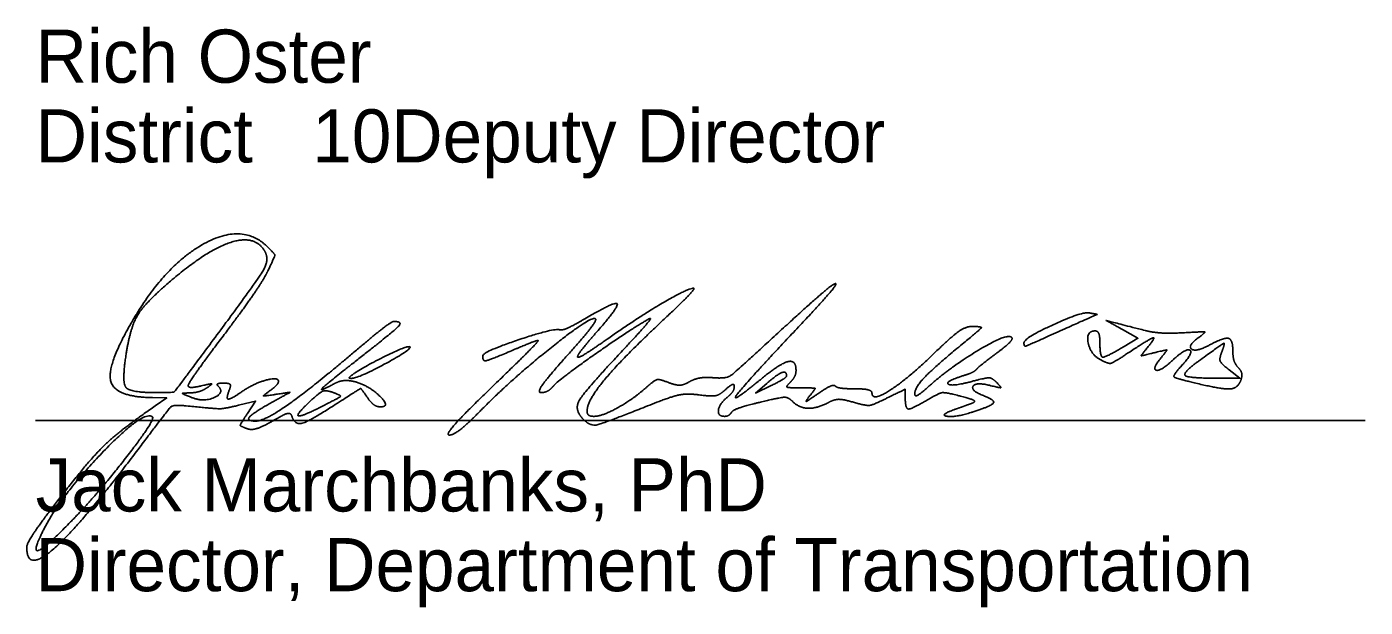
# Model space of a CAD drawing. Extents: x 21.4 to 65.3, y 4 to 26.
# Drawn here: x 45.952 to 49.475, y 11.259 to 12.788 of the extents above; entities that cross this region are included whole.
import ezdxf

# ---------------------------------------------------------------- set-up
doc = ezdxf.new("R2010")
doc.units = 0
doc.layers.add('SH_Data', color=7, linetype='Continuous')
doc.layers.add('SH_Text', color=7, linetype='Continuous')

msp = doc.modelspace()

# ---------------------------------------------------------------- linework, layer by layer
at = {"layer": 'SH_Data'}
msp.add_line((45.9752, 11.751), (49.4752, 11.751), dxfattribs=at)
at = {"layer": 'SH_Text'}
for p, q in [((46.4375, 11.956), (46.4375, 11.956)), ((48.5768, 11.9552), (48.5768, 11.9552)), ((46.8028, 11.8662), (46.8028, 11.8662)), ((47.9518, 11.8682), (47.9518, 11.8682)), ((49.0293, 11.8489), (49.0293, 11.8489)), ((46.758, 11.8245), (46.758, 11.8245)), ((47.1747, 11.8371), (47.1747, 11.8371))]:
    msp.add_line(p, q, dxfattribs=at)
for points in [[(48.8406, 11.9456), (48.877, 11.9671), (48.8363, 11.99)], [(49.0893, 11.8621), (49.1455, 11.8621), (49.1168, 11.8843)], [(47.9001, 11.8485), (47.8705, 11.8229), (47.9112, 11.8425)], [(46.2899, 11.7891), (46.3205, 11.8103), (46.2827, 11.8109)], [(46.5328, 11.7692), (46.554, 11.8016), (46.5123, 11.7915)]]:
    msp.add_lwpolyline(points, dxfattribs=at)
for points in [[(46.2262, 12.0068), (46.3124, 12.1571), (46.5206, 12.2732), (46.5862, 12.2075)], [(46.5773, 12.1983), (46.5513, 12.2403), (46.4252, 12.1992), (46.3299, 12.1176)], [(46.4375, 11.956), (46.5589, 12.1195), (46.5913, 12.1757), (46.5773, 12.1983)], [(46.5862, 12.2075), (46.605, 12.1887), (46.605, 12.1837), (46.5867, 12.1453)], [(46.5867, 12.1453), (46.5758, 12.1223), (46.524, 12.0467), (46.4718, 11.9774)], [(46.3299, 12.1176), (46.2632, 12.0605), (46.2244, 11.9964), (46.2133, 11.9252)], [(47.4799, 11.9652), (47.5605, 12.0219), (47.6918, 12.0991), (47.7075, 12.0991)], [(47.7075, 12.0991), (47.7124, 12.0991), (47.6711, 12.0565), (47.6157, 12.0044)], [(47.9342, 11.9857), (48.0092, 12.0547), (48.0752, 12.1114), (48.081, 12.1114)], [(48.081, 12.1114), (48.0867, 12.1115), (48.0347, 12.0514), (47.9653, 11.9778)], [(47.421, 12.0187), (47.4997, 12.0649), (47.512, 12.0517), (47.4527, 11.9844)], [(47.449, 12.0185), (47.4394, 12.0281), (47.2297, 11.8612), (47.1518, 11.7819)], [(47.5893, 12.0181), (47.5403, 11.9903), (47.3519, 11.858), (47.3387, 11.8421)], [(47.3553, 11.9895), (47.3609, 11.9877), (47.3904, 12.0008), (47.421, 12.0187)], [(47.3712, 11.9181), (47.4175, 11.9699), (47.4525, 12.015), (47.449, 12.0185)], [(47.5241, 11.9391), (47.5703, 11.9884), (47.5996, 12.0239), (47.5893, 12.0181)], [(48.5768, 11.9552), (48.5768, 11.9676), (48.7296, 12.0379), (48.7485, 12.0342)], [(48.7485, 12.0342), (48.7692, 12.0301), (48.77, 12.0306), (48.6483, 11.9759)], [(46.2827, 11.8109), (46.1848, 11.8126), (46.1614, 11.8938), (46.2262, 12.0068)], [(46.8163, 11.9333), (46.8668, 11.9761), (46.9123, 12.0113), (46.9174, 12.0114)], [(46.9174, 12.0114), (46.9423, 12.0119), (46.9189, 11.9863), (46.833, 11.9191)], [(47.152, 11.921), (47.1522, 11.9315), (47.3396, 11.9947), (47.3553, 11.9895)], [(47.4527, 11.9844), (47.4247, 11.9525), (47.4018, 11.9229), (47.4018, 11.9184)], [(47.6157, 12.0044), (47.5161, 11.9107), (47.4268, 11.8025), (47.4268, 11.7755)], [(47.7592, 11.8633), (47.7927, 11.8605), (47.8162, 11.8769), (47.9342, 11.9857)], [(48.3424, 11.9294), (48.3876, 11.9732), (48.4248, 11.9989), (48.4424, 11.9985)], [(48.4424, 11.9985), (48.4667, 11.998), (48.4629, 11.9917), (48.4143, 11.9517)], [(48.7778, 11.911), (48.7513, 11.9252), (48.7403, 11.9866), (48.7643, 11.9866)], [(48.7643, 11.9866), (48.7712, 11.9866), (48.7768, 11.9725), (48.7768, 11.9553)], [(48.8363, 11.99), (48.7934, 12.0142), (48.7925, 12.0142), (48.8955, 11.9878)], [(48.8955, 11.9878), (48.9162, 11.9825), (48.9612, 11.9798), (48.9955, 11.9817)], [(48.9955, 11.9817), (49.0504, 11.9848), (49.0553, 11.9831), (49.0354, 11.9683)], [(46.2914, 11.8241), (46.3381, 11.8241), (46.3426, 11.8282), (46.4375, 11.956)], [(46.4718, 11.9774), (46.4195, 11.908), (46.3768, 11.8473), (46.3768, 11.8426)], [(46.8028, 11.8662), (46.8232, 11.884), (46.9553, 11.9498), (46.9604, 11.9446)], [(46.9604, 11.9446), (46.9666, 11.9385), (46.824, 11.8616), (46.8063, 11.8616)], [(47.1747, 11.8371), (47.2457, 11.9056), (47.301, 11.9616), (47.2976, 11.9616)], [(47.2976, 11.9616), (47.2942, 11.9616), (47.2651, 11.9503), (47.233, 11.9366)], [(47.4018, 11.9184), (47.4018, 11.914), (47.437, 11.935), (47.4799, 11.9652)], [(47.9653, 11.9778), (47.8358, 11.8402), (47.8037, 11.7929), (47.8859, 11.8607)], [(48.4143, 11.9517), (48.3403, 11.8907), (48.2893, 11.8372), (48.2893, 11.8204)], [(48.3237, 11.8382), (48.3773, 11.887), (48.5242, 11.977), (48.5411, 11.9714)], [(48.5411, 11.9714), (48.5495, 11.9686), (48.5343, 11.9499), (48.5072, 11.9297)], [(48.6483, 11.9759), (48.5858, 11.9478), (48.5768, 11.9452), (48.5768, 11.9552)], [(48.7768, 11.9553), (48.7768, 11.9185), (48.7911, 11.9163), (48.8406, 11.9456)], [(48.9002, 11.9408), (48.9246, 11.9704), (48.9088, 11.9666), (48.8525, 11.9294)], [(49.0354, 11.9683), (49.0066, 11.9469), (49.0295, 11.9305), (49.0632, 11.9485)], [(49.0971, 11.9298), (49.107, 11.9556), (49.0987, 11.9525), (49.0361, 11.9069)], [(49.0632, 11.9485), (49.1034, 11.97), (49.1268, 11.9643), (49.1268, 11.9328)], [(46.2133, 11.9252), (46.2019, 11.8518), (46.2233, 11.8241), (46.2914, 11.8241)], [(46.555, 11.7491), (46.578, 11.7491), (46.7041, 11.8379), (46.8163, 11.9333)], [(46.833, 11.9191), (46.7398, 11.8461), (46.7184, 11.8245), (46.7623, 11.848)], [(47.233, 11.9366), (47.1704, 11.9098), (47.1517, 11.9061), (47.152, 11.921)], [(47.3054, 11.8241), (47.2951, 11.8241), (47.324, 11.8654), (47.3712, 11.9181)], [(47.417, 11.7535), (47.3918, 11.7787), (47.4207, 11.8288), (47.5241, 11.9391)], [(48.1768, 11.8226), (48.1768, 11.7998), (48.2721, 11.8612), (48.3424, 11.9294)], [(48.5072, 11.9297), (48.4802, 11.9095), (48.4552, 11.8895), (48.4518, 11.8852)], [(48.8525, 11.9294), (48.8125, 11.9028), (48.7992, 11.8996), (48.7778, 11.911)], [(48.9196, 11.9291), (48.8865, 11.9208), (48.8847, 11.9219), (48.9002, 11.9408)], [(48.9397, 11.9183), (48.9543, 11.9359), (48.952, 11.9371), (48.9196, 11.9291)], [(48.9684, 11.9096), (48.9365, 11.8796), (48.9134, 11.8866), (48.9397, 11.9183)], [(48.9936, 11.8969), (49.0241, 11.9306), (49.0024, 11.9415), (48.9684, 11.9096)], [(49.1168, 11.8843), (49.0964, 11.8999), (49.0907, 11.9132), (49.0971, 11.9298)], [(49.1268, 11.9328), (49.1268, 11.917), (49.1332, 11.8977), (49.141, 11.8899)], [(47.8859, 11.8607), (47.9343, 11.9006), (47.9768, 11.9109), (47.9768, 11.8828)], [(47.9518, 11.8682), (47.9518, 11.8816), (47.9277, 11.8725), (47.9001, 11.8485)], [(47.9768, 11.8828), (47.9768, 11.8739), (47.97, 11.8598), (47.9618, 11.8516)], [(48.4518, 11.8852), (48.4484, 11.881), (48.4329, 11.8735), (48.4174, 11.8687)], [(49.0293, 11.8489), (48.9746, 11.8619), (48.9688, 11.8696), (48.9936, 11.8969)], [(49.0361, 11.9069), (48.9934, 11.8758), (49.0099, 11.8619), (49.0893, 11.8621)], [(49.141, 11.8899), (49.1487, 11.8821), (49.1517, 11.867), (49.1476, 11.8562)], [(46.3768, 11.8426), (46.3768, 11.8378), (46.3923, 11.8375), (46.4112, 11.8419)], [(46.3872, 11.8108), (46.4171, 11.7988), (46.4733, 11.8234), (46.4559, 11.8408)], [(46.4112, 11.8419), (46.4367, 11.8478), (46.4407, 11.8466), (46.4268, 11.8372)], [(46.4559, 11.8408), (46.4513, 11.8454), (46.4576, 11.8491), (46.4698, 11.8491)], [(46.4698, 11.8491), (46.4844, 11.8491), (46.4895, 11.8427), (46.4848, 11.8303)], [(46.5209, 11.8285), (46.5498, 11.8483), (46.6143, 11.8658), (46.6143, 11.8538)], [(46.6143, 11.8538), (46.6143, 11.8493), (46.6046, 11.8385), (46.5927, 11.8298)], [(46.7623, 11.848), (46.7749, 11.8548), (46.7988, 11.8569), (46.8154, 11.8527)], [(46.8063, 11.8616), (46.8015, 11.8616), (46.8, 11.8636), (46.8028, 11.8662)], [(46.8154, 11.8527), (46.8515, 11.8435), (46.9099, 11.7866), (46.8832, 11.7866)], [(47.3387, 11.8421), (47.3305, 11.8322), (47.3155, 11.8241), (47.3054, 11.8241)], [(47.4448, 11.7616), (47.4666, 11.7616), (47.5479, 11.8068), (47.5843, 11.8391)], [(47.5843, 11.8391), (47.6046, 11.8571), (47.6175, 11.8598), (47.6412, 11.8507)], [(47.6412, 11.8507), (47.6614, 11.8431), (47.6802, 11.8438), (47.6962, 11.8528)], [(47.6962, 11.8528), (47.7096, 11.8604), (47.7379, 11.8651), (47.7592, 11.8633)], [(47.8143, 11.8401), (47.8143, 11.8472), (47.8041, 11.8438), (47.7917, 11.8325)], [(47.7955, 11.8116), (47.8059, 11.8201), (47.8143, 11.833), (47.8143, 11.8401)], [(47.9112, 11.8425), (47.9335, 11.8534), (47.9518, 11.8649), (47.9518, 11.8682)], [(47.9618, 11.8516), (47.9501, 11.8399), (47.956, 11.8366), (47.9883, 11.8366)], [(48.0345, 11.8211), (48.0559, 11.8361), (48.0766, 11.8451), (48.0805, 11.8412)], [(48.0805, 11.8412), (48.0844, 11.8373), (48.1077, 11.8341), (48.1322, 11.8341)], [(48.4174, 11.8687), (48.3679, 11.8532), (48.3874, 11.8396), (48.4392, 11.8534)], [(48.4392, 11.8534), (48.4776, 11.8636), (48.4928, 11.863), (48.5049, 11.8508)], [(48.4862, 11.8433), (48.4494, 11.8524), (48.4362, 11.8293), (48.4705, 11.8161)], [(48.5049, 11.8508), (48.5175, 11.8379), (48.514, 11.8364), (48.4862, 11.8433)], [(49.1476, 11.8562), (49.1395, 11.8351), (49.0983, 11.8326), (49.0293, 11.8489)], [(46.383, 11.8235), (46.3606, 11.8226), (46.3611, 11.8213), (46.3872, 11.8108)], [(46.4268, 11.8372), (46.4165, 11.8302), (46.3968, 11.824), (46.383, 11.8235)], [(46.4848, 11.8303), (46.4759, 11.8071), (46.4887, 11.8064), (46.5209, 11.8285)], [(46.5927, 11.8298), (46.5738, 11.816), (46.5757, 11.8147), (46.6083, 11.8196)], [(46.6083, 11.8196), (46.6451, 11.8251), (46.645, 11.8249), (46.5995, 11.7998)], [(46.7049, 11.808), (46.6607, 11.7675), (46.6719, 11.7586), (46.7299, 11.7882)], [(46.758, 11.8245), (46.7408, 11.8308), (46.7243, 11.8257), (46.7049, 11.808)], [(46.7299, 11.7882), (46.7763, 11.8119), (46.7799, 11.8165), (46.758, 11.8245)], [(46.8484, 11.8113), (46.8316, 11.8353), (46.8295, 11.8349), (46.7638, 11.7925)], [(46.8832, 11.7866), (46.8736, 11.7866), (46.8579, 11.7977), (46.8484, 11.8113)], [(47.0643, 11.7123), (47.054, 11.7125), (47.1036, 11.7687), (47.1747, 11.8371)], [(47.7222, 11.8181), (47.693, 11.8219), (47.6532, 11.8154), (47.6167, 11.801)], [(47.7917, 11.8325), (47.7761, 11.8184), (47.7548, 11.8139), (47.7222, 11.8181)], [(47.7886, 11.7616), (47.7702, 11.7616), (47.7748, 11.7943), (47.7955, 11.8116)], [(47.9672, 11.8012), (47.9561, 11.8123), (47.936, 11.8118), (47.8829, 11.799)], [(47.9883, 11.8366), (48.0259, 11.8366), (48.0282, 11.8345), (48.0127, 11.8152)], [(48.0127, 11.8152), (48.0007, 11.8002), (48.0072, 11.802), (48.0345, 11.8211)], [(48.128, 11.7987), (48.1011, 11.8065), (48.078, 11.8064), (48.0635, 11.7987)], [(48.2171, 11.8101), (48.1797, 11.7916), (48.1611, 11.7892), (48.128, 11.7987)], [(48.1322, 11.8341), (48.1567, 11.8341), (48.1768, 11.8289), (48.1768, 11.8226)], [(48.2643, 11.81), (48.2643, 11.8329), (48.2632, 11.8329), (48.2171, 11.8101)], [(48.3262, 11.807), (48.2812, 11.7804), (48.2643, 11.7812), (48.2643, 11.81)], [(48.2893, 11.8204), (48.2893, 11.813), (48.3048, 11.821), (48.3237, 11.8382)], [(48.4094, 11.815), (48.3706, 11.8249), (48.3538, 11.8233), (48.3262, 11.807)], [(48.4393, 11.7958), (48.4507, 11.8), (48.439, 11.8075), (48.4094, 11.815)], [(48.4705, 11.8161), (48.5011, 11.8044), (48.4922, 11.7895), (48.4454, 11.7741)], [(46.0389, 11.5469), (46.1166, 11.6473), (46.1967, 11.7246), (46.2899, 11.7891)], [(46.3711, 11.7892), (46.3377, 11.7925), (46.3259, 11.782), (46.2493, 11.6803)], [(46.5123, 11.7915), (46.4719, 11.7817), (46.4496, 11.7814), (46.3711, 11.7892)], [(46.5316, 11.7292), (46.5134, 11.7361), (46.5135, 11.7398), (46.5328, 11.7692)], [(46.5995, 11.7998), (46.5484, 11.7716), (46.5287, 11.7491), (46.555, 11.7491)], [(46.6493, 11.7628), (46.6465, 11.7713), (46.6272, 11.7661), (46.5982, 11.749)], [(46.7638, 11.7925), (46.6949, 11.7481), (46.6574, 11.7384), (46.6493, 11.7628)], [(47.1518, 11.7819), (47.114, 11.7434), (47.0746, 11.7121), (47.0643, 11.7123)], [(47.6167, 11.801), (47.4706, 11.7433), (47.4356, 11.735), (47.417, 11.7535)], [(47.4268, 11.7755), (47.4268, 11.7679), (47.4349, 11.7616), (47.4448, 11.7616)], [(47.8067, 11.772), (47.8032, 11.7663), (47.795, 11.7616), (47.7886, 11.7616)], [(47.8829, 11.799), (47.8445, 11.7898), (47.8102, 11.7777), (47.8067, 11.772)], [(48.0635, 11.7987), (48.0328, 11.7822), (47.9849, 11.7835), (47.9672, 11.8012)], [(48.4454, 11.7741), (48.3988, 11.7587), (48.3515, 11.7644), (48.3955, 11.7801)], [(48.3955, 11.7801), (48.4093, 11.785), (48.429, 11.7921), (48.4393, 11.7958)], [(46.2827, 11.7598), (46.2618, 11.7807), (46.0433, 11.5551), (45.997, 11.4647)], [(46.0671, 11.4835), (46.1347, 11.5525), (46.2904, 11.7521), (46.2827, 11.7598)], [(46.5982, 11.749), (46.5725, 11.7339), (46.5426, 11.725), (46.5316, 11.7292)], [(46.2493, 11.6803), (46.0969, 11.4783), (45.9518, 11.3496), (45.9518, 11.4166)], [(45.9518, 11.4166), (45.9518, 11.4263), (45.991, 11.4849), (46.0389, 11.5469)], [(45.997, 11.4647), (45.9657, 11.4038), (45.9974, 11.4122), (46.0671, 11.4835)]]:
    msp.add_open_spline(points, degree=2, dxfattribs=at)

# ---------------------------------------------------------------- texts
for s, p in [('Rich Oster', (45.9752, 12.6404)), ('District       Deputy Director', (45.9752, 12.4304)), ('              10', (45.9752, 12.4304)), ('Jack Marchbanks, PhD', (45.9752, 11.511)), ('Director, Department of Transportation', (45.9752, 11.301))]:
    msp.add_text(s, height=0.14, dxfattribs=at).set_placement(p)

doc.saveas('drawing.dxf')
